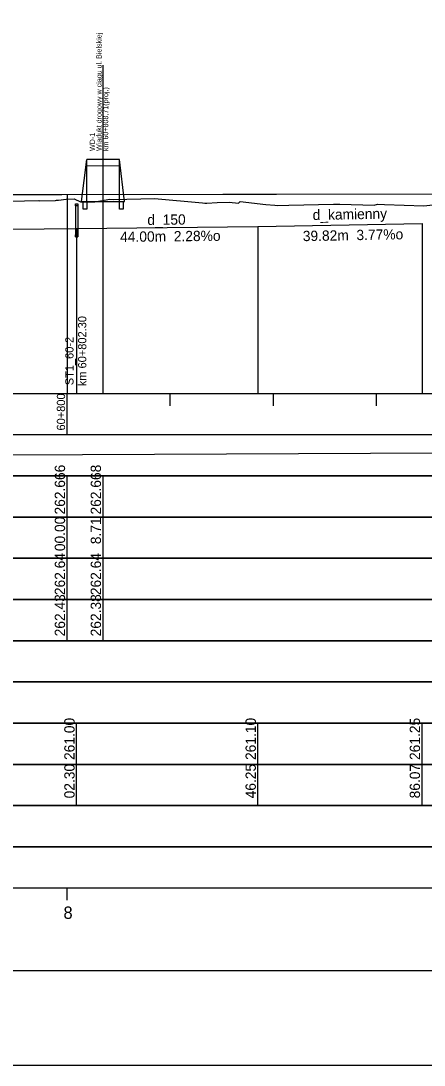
# Model space of a CAD drawing. Extents: x 6445630 to 6518227, y 5499240 to 5511716.
# Drawn here: x 6460020 to 6460117.8, y 5508966.7 to 5509220.2 of the extents above; entities that cross this region are included whole.
import ezdxf

# ---------------------------------------------------------------- set-up
doc = ezdxf.new("R2010")
doc.units = 0
for name, color, linetype in [('Default', 7, 'Continuous'), ('TOR_PROF-drenaze', 7, 'Continuous'), ('TOR_PROF-drenokolektory', 7, 'Continuous'), ('TOR_PROF-obiekty+opisy', 7, 'Continuous'), ('TOR_PROF-opisy glowne', 7, 'Continuous'), ('TOR_PROF-studnie i osadniki', 7, 'Continuous'), ('TOR_PROF-tabelka-geometria T1', 7, 'Continuous'), ('TOR_PROF-tabelka-kilometracja', 7, 'Continuous'), ('TOR_PROF-tabelka-odleglosci T1', 7, 'Continuous'), ('TOR_PROF-tabelka-pochylenia proj T1', 7, 'Continuous'), ('TOR_PROF-tabelka-rodzaj rowu T1', 7, 'Continuous'), ('TOR_PROF-tabelka-rodzaj rurociagow T1', 7, 'Continuous'), ('TOR_PROF-tabelka-rowyT1', 7, 'Continuous'), ('TOR_PROF-tabelka-rurociagi T1', 7, 'Continuous'), ('TOR_PROF-tabelka-rzedne istn T1', 7, 'Continuous'), ('TOR_PROF-tabelka-rzedne proj T1', 7, 'Continuous'), ('TOR_PROF-tabelka-teren istniejacy T1', 7, 'Continuous'), ('TOR_PROF-tabelka-warstwa ochronna T1', 7, 'Continuous'), ('TOR_PROF-tor istniejacy T1', 7, 'Continuous'), ('TOR_PROF-tor projektowany', 7, 'Continuous'), ('TOR_PROF-uklad odniesienia', 7, 'Continuous'), ('TOR_PROF-warstwa ochronna', 7, 'Continuous'), ('TOR_RAMKI-dodatkowe3', 7, 'Continuous'), ('TOR_RAMKI-MASKA WYCIECIA', 7, 'Continuous')]:
    doc.layers.add(name, color=color, linetype=linetype)

msp = doc.modelspace()

# ---------------------------------------------------------------- linework, layer by layer
at = {"layer": 'TOR_PROF-drenaze'}
for points in [[(6459978.32, 5509169.24), (6460033.52, 5509169.74)], [(6460033.52, 5509169.74), (6460077.47, 5509170.24)], [(6460077.47, 5509170.24), (6460117.28, 5509170.99)]]:
    msp.add_lwpolyline(points, dxfattribs=at)
at = {"layer": 'TOR_PROF-drenokolektory'}
for points in [[(6460033.52, 5509169.74), (6460033.52, 5509134.74), (6460033.52, 5509129.74), (6460033.52, 5509129.74)], [(6460033.52, 5509169.74), (6460033.52, 5509134.74), (6460033.52, 5509129.74), (6460033.52, 5509129.74)], [(6460033.52, 5509169.74), (6460033.52, 5509134.74), (6460033.52, 5509129.74), (6460033.52, 5509129.74)], [(6460077.47, 5509170.24), (6460077.47, 5509134.74), (6460077.47, 5509129.74), (6460077.47, 5509129.74)], [(6460077.47, 5509170.24), (6460077.47, 5509134.74), (6460077.47, 5509129.74), (6460077.47, 5509129.74)], [(6460077.47, 5509170.24), (6460077.47, 5509134.74), (6460077.47, 5509129.74), (6460077.47, 5509129.74)], [(6460117.28, 5509170.99), (6460117.28, 5509134.74), (6460117.28, 5509129.74), (6460117.28, 5509129.74)], [(6460117.28, 5509170.99), (6460117.28, 5509134.74), (6460117.28, 5509129.74), (6460117.28, 5509129.74)]]:
    msp.add_lwpolyline(points, dxfattribs=at)
at = {"layer": 'TOR_PROF-obiekty+opisy'}
for p, q in [((6460039.92, 5509129.74), (6460039.92, 5509209.38)), ((6460034.72, 5509176.37), (6460035.97, 5509186.53)), ((6460043.88, 5509186.53), (6460035.97, 5509186.53)), ((6460035.97, 5509176.37), (6460035.97, 5509186.53)), ((6460045.13, 5509176.37), (6460043.88, 5509186.53)), ((6460043.88, 5509176.37), (6460043.88, 5509186.53)), ((6460043.88, 5509184.94), (6460035.97, 5509184.95)), ((6460034.72, 5509176.37), (6460045.13, 5509176.37))]:
    msp.add_line(p, q, dxfattribs=at)
for points in [[(6460035.97, 5509176.37), (6460035.97, 5509174.5), (6460035.1, 5509174.5), (6460035.1, 5509176.37)], [(6460044.76, 5509176.37), (6460044.76, 5509174.5), (6460043.88, 5509174.5), (6460043.88, 5509176.37)]]:
    msp.add_lwpolyline(points, close=True, dxfattribs=at)
at = {"layer": 'TOR_PROF-studnie i osadniki'}
for p, q in [((6460033.27, 5509175.74), (6460033.27, 5509167.74)), ((6460033.27, 5509175.74), (6460033.77, 5509175.74)), ((6460033.77, 5509175.74), (6460033.77, 5509167.74)), ((6460033.27, 5509167.74), (6460033.77, 5509167.74))]:
    msp.add_line(p, q, dxfattribs=at)
for points in [[(6460033.27, 5509175.74), (6460033.77, 5509175.74), (6460033.77, 5509175.24), (6460033.27, 5509175.24)], [(6460033.27, 5509168.24), (6460033.77, 5509168.24), (6460033.77, 5509167.74), (6460033.27, 5509167.74)]]:
    msp.add_lwpolyline(points, close=True, dxfattribs=at)
at = {"layer": 'TOR_PROF-tabelka-geometria T1'}
for points in [[(6452331.21, 5508989.74), (6462728.4, 5508989.74)], [(6452331.21, 5508989.74), (6462731.21, 5508989.74)]]:
    msp.add_lwpolyline(points, dxfattribs=at)
at = {"layer": 'TOR_PROF-tabelka-kilometracja'}
msp.add_lwpolyline([(6460031.21, 5509006.74), (6460031.21, 5509009.74)], dxfattribs=at)
at = {"layer": 'TOR_PROF-tabelka-odleglosci T1'}
for points in [[(6460031.21, 5509099.74), (6460031.21, 5509109.74)], [(6460039.92, 5509099.74), (6460039.92, 5509109.74)], [(6460031.21, 5509089.74), (6460031.21, 5509099.74)], [(6460039.92, 5509089.74), (6460039.92, 5509099.74)]]:
    msp.add_lwpolyline(points, dxfattribs=at)
msp.add_lwpolyline([(6452331.21, 5509089.74), (6462731.21, 5509089.74), (6462731.21, 5509099.74), (6452331.21, 5509099.74)], close=True, dxfattribs=at)
at = {"layer": 'TOR_PROF-tabelka-pochylenia proj T1'}
msp.add_lwpolyline([(6452331.21, 5509109.74), (6462731.21, 5509109.74), (6462731.21, 5509119.74), (6452331.21, 5509119.74)], close=True, dxfattribs=at)
msp.add_lwpolyline([(6459231.21, 5509111.24), (6460751.21, 5509118.24)], dxfattribs=at)
at = {"layer": 'TOR_PROF-tabelka-rodzaj rowu T1'}
for points in [[(6452331.21, 5509049.74), (6462731.21, 5509049.74), (6462731.21, 5509059.74), (6452331.21, 5509059.74)], [(6452331.21, 5509029.74), (6462731.21, 5509029.74), (6462731.21, 5509039.74), (6452331.21, 5509039.74)]]:
    msp.add_lwpolyline(points, close=True, dxfattribs=at)
for points in [[(6460033.52, 5509029.74), (6460033.52, 5509039.74)], [(6460077.47, 5509029.74), (6460077.47, 5509039.74)], [(6460117.28, 5509029.74), (6460117.28, 5509039.74)]]:
    msp.add_lwpolyline(points, dxfattribs=at)
at = {"layer": 'TOR_PROF-tabelka-rowyT1'}
msp.add_lwpolyline([(6452331.21, 5509059.74), (6462731.21, 5509059.74), (6462731.21, 5509069.74), (6452331.21, 5509069.74)], close=True, dxfattribs=at)
at = {"layer": 'TOR_PROF-tabelka-rurociagi T1'}
msp.add_lwpolyline([(6452331.21, 5509039.74), (6462731.21, 5509039.74), (6462731.21, 5509049.74), (6452331.21, 5509049.74)], close=True, dxfattribs=at)
for points in [[(6460033.52, 5509039.74), (6460033.52, 5509049.74)], [(6460077.47, 5509039.74), (6460077.47, 5509049.74)], [(6460117.28, 5509039.74), (6460117.28, 5509049.74)]]:
    msp.add_lwpolyline(points, dxfattribs=at)
at = {"layer": 'TOR_PROF-tabelka-rzedne istn T1'}
msp.add_lwpolyline([(6452331.21, 5509079.74), (6462731.21, 5509079.74), (6462731.21, 5509089.74), (6452331.21, 5509089.74)], close=True, dxfattribs=at)
for points in [[(6460031.21, 5509079.74), (6460031.21, 5509089.74)], [(6460039.92, 5509079.74), (6460039.92, 5509089.74)], [(6460031.21, 5509069.74), (6460031.21, 5509079.74)], [(6460031.21, 5509069.74), (6460031.21, 5509079.74)], [(6460031.21, 5509069.74), (6460031.21, 5509079.74)], [(6460031.21, 5509069.74), (6460031.21, 5509079.74)], [(6460031.21, 5509069.74), (6460031.21, 5509079.74)], [(6460039.92, 5509069.74), (6460039.92, 5509079.74)]]:
    msp.add_lwpolyline(points, dxfattribs=at)
at = {"layer": 'TOR_PROF-tabelka-rzedne proj T1'}
msp.add_lwpolyline([(6452331.21, 5509099.74), (6462731.21, 5509099.74), (6462731.21, 5509109.74), (6452331.21, 5509109.74)], close=True, dxfattribs=at)
at = {"layer": 'TOR_PROF-tabelka-teren istniejacy T1'}
msp.add_lwpolyline([(6452331.21, 5509069.74), (6462731.21, 5509069.74), (6462731.21, 5509079.74), (6452331.21, 5509079.74)], close=True, dxfattribs=at)
msp.add_lwpolyline([(6452331.21, 5509069.74), (6462731.21, 5509069.74), (6462731.21, 5509079.74), (6452331.21, 5509079.74)], close=True, dxfattribs=at)
msp.add_lwpolyline([(6452331.21, 5509069.74), (6462731.21, 5509069.74), (6462731.21, 5509079.74), (6452331.21, 5509079.74)], close=True, dxfattribs=at)
msp.add_lwpolyline([(6452331.21, 5509069.74), (6462731.21, 5509069.74), (6462731.21, 5509079.74), (6452331.21, 5509079.74)], close=True, dxfattribs=at)
msp.add_lwpolyline([(6452331.21, 5509069.74), (6462731.21, 5509069.74), (6462731.21, 5509079.74), (6452331.21, 5509079.74)], close=True, dxfattribs=at)
at = {"layer": 'TOR_PROF-tabelka-warstwa ochronna T1'}
msp.add_lwpolyline([(6452331.21, 5509019.74), (6462731.21, 5509019.74), (6462731.21, 5509029.74), (6452331.21, 5509029.74)], close=True, dxfattribs=at)
at = {"layer": 'TOR_PROF-tor istniejacy T1'}
msp.add_lwpolyline([(6460704.37, 5509178.58), (6460688.84, 5509178.51), (6460647.25, 5509178.18), (6460634.91, 5509178.09), (6460584.94, 5509177.84), (6460534.2, 5509177.64), (6460484.5, 5509177.69), (6460434.32, 5509177.84), (6460384.44, 5509177.94), (6460334.72, 5509177.99), (6460316.15, 5509177.94), (6460285.09, 5509177.99), (6460235.86, 5509177.99), (6460183.29, 5509178.09), (6460134.2, 5509178.09), (6460082.01, 5509178.04), (6460029.92, 5509177.94), (6460018.28, 5509177.99), (6459980.19, 5509177.99), (6459929.59, 5509178.14), (6459879.85, 5509178.04), (6459830.31, 5509177.94)], dxfattribs=at)
at = {"layer": 'TOR_PROF-tor projektowany'}
msp.add_line((6459231.21, 5509176.99), (6460751.21, 5509179.04), dxfattribs=at)
msp.add_line((6459231.21, 5509176.99), (6460751.21, 5509179.04), dxfattribs=at)
msp.add_lwpolyline([(6460031.21, 5509178.06), (6460031.21, 5509134.74), (6460031.21, 5509129.74), (6460031.21, 5509129.74)], dxfattribs=at)
msp.add_lwpolyline([(6460031.21, 5509178.06), (6460031.21, 5509134.74), (6460031.21, 5509129.74), (6460031.21, 5509129.74)], dxfattribs=at)
at = {"layer": 'TOR_PROF-uklad odniesienia'}
for p, q in [((6452331.21, 5509129.74), (6462731.21, 5509129.74)), ((6460031.21, 5509119.74), (6460031.21, 5509129.74)), ((6460056.21, 5509126.74), (6460056.21, 5509129.74)), ((6460081.21, 5509126.74), (6460081.21, 5509129.74)), ((6460106.21, 5509126.74), (6460106.21, 5509129.74))]:
    msp.add_line(p, q, dxfattribs=at)
at = {"layer": 'TOR_PROF-warstwa ochronna'}
msp.add_lwpolyline([(6452331.21, 5509009.74), (6462731.21, 5509009.74), (6462731.21, 5509019.74), (6452331.21, 5509019.74)], close=True, dxfattribs=at)
at = {"layer": 'TOR_RAMKI-dodatkowe3'}
for p, q in [((6460005.53, 5509176.33), (6460020.84, 5509176.5)), ((6460020.84, 5509176.5), (6460024.31, 5509176.54)), ((6460024.31, 5509176.54), (6460024.42, 5509176.52)), ((6460024.42, 5509176.52), (6460028.42, 5509176.6)), ((6460028.42, 5509176.6), (6460028.6, 5509176.62)), ((6460028.6, 5509176.62), (6460029.11, 5509176.67)), ((6460029.11, 5509176.67), (6460030.98, 5509176.87)), ((6460030.98, 5509176.87), (6460032.88, 5509177)), ((6460032.88, 5509177), (6460034.43, 5509176.22)), ((6460034.43, 5509176.22), (6460037.91, 5509176.27)), ((6460037.91, 5509176.27), (6460041.57, 5509176.9)), ((6460041.57, 5509176.9), (6460042.38, 5509176.83)), ((6460042.38, 5509176.83), (6460052.4, 5509177.02)), ((6460052.4, 5509177.02), (6460064.01, 5509176)), ((6460072.79, 5509175.9), (6460073.15, 5509176.31)), ((6460073.15, 5509176.31), (6460079.38, 5509175.57)), ((6460064.01, 5509176), (6460064.62, 5509175.94)), ((6460064.62, 5509175.94), (6460065.07, 5509175.89)), ((6460065.07, 5509175.89), (6460067.63, 5509176.11)), ((6460067.63, 5509176.11), (6460070.52, 5509176.18)), ((6460070.52, 5509176.18), (6460072.79, 5509175.9)), ((6460079.38, 5509175.57), (6460081.55, 5509175.43)), ((6460081.55, 5509175.43), (6460082.19, 5509175.37)), ((6460082.19, 5509175.37), (6460084.94, 5509175.43)), ((6460084.94, 5509175.43), (6460095.82, 5509175.68)), ((6460095.82, 5509175.68), (6460097.36, 5509175.66)), ((6460097.36, 5509175.66), (6460105.69, 5509175.47)), ((6460105.69, 5509175.47), (6460106.44, 5509175.66)), ((6460106.44, 5509175.66), (6460108.2, 5509175.62)), ((6460108.2, 5509175.62), (6460117.73, 5509175.25)), ((6460117.73, 5509175.25), (6460123.61, 5509175.93))]:
    msp.add_line(p, q, dxfattribs=at)
at = {"layer": 'TOR_RAMKI-MASKA WYCIECIA'}
msp.add_lwpolyline([(6459211.14, 5508966.75), (6460761.14, 5508966.75), (6460761.14, 5509253.75), (6459211.14, 5509253.75)], close=True, dxfattribs=at)

# ---------------------------------------------------------------- texts
at = {"layer": 'Default'}
for p in [(6460029.92, 5509177.94), (6460082.01, 5509178.04)]:
    msp.add_text('+', height=0.001, dxfattribs=at).set_placement(p)
at = {"layer": 'TOR_PROF-drenaze'}
for s, rotation, p in [('d_kamienny', 1.0791, (6460090.77, 5509171.83)), ('d_150', 0.519, (6460050.67, 5509170.64)), ('44.00m  2.28%o  ', 0.6518, (6460044.08, 5509166.51)), ('39.82m  3.77%o  ', 1.0791, (6460088.38, 5509166.7))]:
    msp.add_text(s, height=2.5, rotation=rotation, dxfattribs=at).set_placement(p)
at = {"layer": 'TOR_PROF-obiekty+opisy'}
for s, p in [('Wiadukt drogowy w ciągu ul. Bielskiej', (6460039.55, 5509188.59)), ('km 60+808,71(proj.)', (6460041.17, 5509188.59)), ('WD-1', (6460037.94, 5509188.59))]:
    msp.add_text(s, height=1.25, rotation=90, dxfattribs=at).set_placement(p)
at = {"layer": 'TOR_PROF-opisy glowne'}
for s, p in [('km 60+802.30', (6460035.86, 5509131.51)), ('ST1_60-2', (6460032.76, 5509131.74))]:
    msp.add_text(s, height=2, rotation=90, dxfattribs=at).set_placement(p)
at = {"layer": 'TOR_PROF-tabelka-kilometracja'}
msp.add_text('8', height=3, dxfattribs=at).set_placement((6460030.32, 5509002.24))
at = {"layer": 'TOR_PROF-tabelka-odleglosci T1'}
for s, p in [('262.666', (6460030.71, 5509100.37)), ('262.668', (6460039.42, 5509100.37)), ('00.00', (6460030.71, 5509091.48)), ('8.71', (6460039.42, 5509093.17))]:
    msp.add_text(s, height=2.5, rotation=90, dxfattribs=at).set_placement(p)
at = {"layer": 'TOR_PROF-tabelka-rodzaj rurociagow T1'}
for s, p in [('02.30', (6460033.02, 5509031.48)), ('46.25', (6460076.97, 5509031.48)), ('86.07', (6460116.78, 5509031.48))]:
    msp.add_text(s, height=2.5, rotation=90, dxfattribs=at).set_placement(p)
at = {"layer": 'TOR_PROF-tabelka-rurociagi T1'}
for s, p in [('261.00', (6460033.02, 5509040.8)), ('261.10', (6460076.97, 5509040.8)), ('261.25', (6460116.78, 5509040.8))]:
    msp.add_text(s, height=2.5, rotation=90, dxfattribs=at).set_placement(p)
at = {"layer": 'TOR_PROF-tabelka-rzedne istn T1'}
for s, p in [('262.64', (6460030.71, 5509080.8)), ('262.64', (6460039.42, 5509080.8)), ('262.43', (6460030.71, 5509070.8)), ('262.38', (6460039.42, 5509070.8))]:
    msp.add_text(s, height=2.5, rotation=90, dxfattribs=at).set_placement(p)
at = {"layer": 'TOR_PROF-uklad odniesienia'}
msp.add_text('60+800', height=2, rotation=90, dxfattribs=at).set_placement((6460030.71, 5509120.76))

doc.saveas('drawing.dxf')
